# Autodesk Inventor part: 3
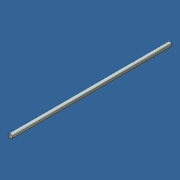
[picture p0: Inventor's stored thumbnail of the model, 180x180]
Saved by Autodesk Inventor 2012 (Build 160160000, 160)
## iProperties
Created: 2013-04
Part Number: 3
Material: Steel
Document SubType Name: Modeling
Designer: Admin
Density: 7.85 g/cm^3
Mass: 14.3037 g
Surface Area: 18.4726 cm^2
Volume: 1.82212 cm^3
Author: Admin
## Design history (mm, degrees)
node "31"
node "3"
node "Base1"
